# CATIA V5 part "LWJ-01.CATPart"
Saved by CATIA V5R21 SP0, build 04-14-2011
Part number: LWJ-01.SLDPRT
Bounding box of the stored display mesh (mm): x -1.362 to 1.338, y -0.976 to 1.024, z 2.1 to 2.7
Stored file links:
  C:\Users\user\Desktop\CATIA文件\0-最新文件(2025.3月之前的慎用)\LWJ-01\LWJ-01.CATPart
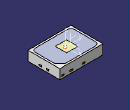
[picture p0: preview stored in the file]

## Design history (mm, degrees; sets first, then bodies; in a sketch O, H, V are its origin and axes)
AxisSystem1: origin (-0.0115, 0.0244, 2.7), X (0, 1, 0), Y (-1, 0, 0), Z (0, 0, 1)
Set1
  DatumSurface1 to DatumSurface42
  Line1: stored without definition
  Circle1: stored without definition
  Line2: stored without definition
  Circle2: stored without definition
  Line3: stored without definition
  Circle3: stored without definition
  Line4: stored without definition
  Circle4: stored without definition
  Line5: stored without definition
  Circle5: stored without definition
  Line6: stored without definition
  Circle6: stored without definition
  Line7: stored without definition
  Circle7: stored without definition
  Line8: stored without definition
  Line9: stored without definition
  Circle8: stored without definition
  Line10: stored without definition
  Line11: stored without definition
  Circle9: stored without definition
  Line12: stored without definition
  Line13: stored without definition
  Circle10: stored without definition
  Line14 to Line18: stored without definition
  Circle11: stored without definition
  Line19: stored without definition
  Circle12: stored without definition
  Line20: stored without definition
  Circle13: stored without definition
  Line21: stored without definition
  Circle14: stored without definition
  Line22: stored without definition
  Circle15: stored without definition
  Line23: stored without definition
  Circle16: stored without definition
  Line24: stored without definition
  Circle17: stored without definition
  Line25: stored without definition
  Circle18: stored without definition
  Line26: stored without definition
  Circle19: stored without definition
  Line27: stored without definition
  Circle20: stored without definition
  Line28 to Line30: stored without definition
  Circle21: stored without definition
  Line31: stored without definition
  Circle22: stored without definition
  Line32: stored without definition
  Circle23: stored without definition
  Line33: stored without definition
  Circle24: stored without definition
  Line34: stored without definition
  Line35: stored without definition
  Circle25: stored without definition
  Line36: stored without definition
  Circle26: stored without definition
  Line37: stored without definition
  Circle27: stored without definition
  Line38: stored without definition
  Circle28: stored without definition
  Line39: stored without definition
  Circle29: stored without definition
  Line40: stored without definition
  Circle30: stored without definition
  Line41: stored without definition
  Circle31: stored without definition
  Line42: stored without definition
  Circle32: stored without definition
  Line43: stored without definition
  Circle33: stored without definition
  Line44 to Line46: stored without definition
  Circle34: stored without definition
  Line47: stored without definition
  Circle35: stored without definition
  Line48: stored without definition
  Circle36: stored without definition
  Line49: stored without definition
  Circle37: stored without definition
  Line50: stored without definition
  Circle38: stored without definition
  Line51 to Line79: stored without definition
  DatumSurface43 to DatumSurface79
  Line80: stored without definition
  Circle39: stored without definition
  Line81: stored without definition
  Circle40: stored without definition
  Line82: stored without definition
  Circle41: stored without definition
  Line83: stored without definition
  Circle42: stored without definition
  Circle43: stored without definition
  Line84 to Line87: stored without definition
  Circle44: stored without definition
  Line88 to Line90: stored without definition
  Circle45: stored without definition
  Line91 to Line93: stored without definition
  Circle46: stored without definition
  Line94: stored without definition
  Line95: stored without definition
  Circle47: stored without definition
  Line96: stored without definition
  Circle48: stored without definition
  Line97: stored without definition
  Circle49: stored without definition
  Line98 to Line100: stored without definition
  Circle50: stored without definition
  Line101: stored without definition
  Circle51: stored without definition
  Line102: stored without definition
  Circle52: stored without definition
  Line103: stored without definition
  Circle53: stored without definition
  Line104: stored without definition
  Circle54: stored without definition
  Line105 to Line107: stored without definition
  Circle55: stored without definition
  Line108: stored without definition
  Circle56: stored without definition
  Line109 to Line112: stored without definition
  Circle57: stored without definition
  Line113: stored without definition
  Circle58: stored without definition
  Line114: stored without definition
  Circle59: stored without definition
  Line115 to Line117: stored without definition
  Circle60: stored without definition
  Line118: stored without definition
  Circle61: stored without definition
  Line119: stored without definition
  Circle62: stored without definition
  Line120: stored without definition
  Circle63: stored without definition
  Line121: stored without definition
  Circle64: stored without definition
  Line122 to Line124: stored without definition
  Circle65: stored without definition
  Line125: stored without definition
  Circle66: stored without definition
  Line126 to Line153: stored without definition
  DatumSurface80 to DatumSurface154
  DatumCurve1
  DatumCurve2
  Circle67: stored without definition
  Line154: stored without definition
  Circle68: stored without definition
  Line155: stored without definition
  Line156: stored without definition
  Circle69: stored without definition
  Line157: stored without definition
  Circle70: stored without definition
  Line158 to Line160: stored without definition
  Circle71: stored without definition
  Line161: stored without definition
  Circle72: stored without definition
  Line162 to Line164: stored without definition
  Circle73: stored without definition
  Line165: stored without definition
  Circle74: stored without definition
  Line166 to Line168: stored without definition
  Circle75: stored without definition
  Line169: stored without definition
  Circle76: stored without definition
  Line170: stored without definition
  Line171: stored without definition
  Circle77: stored without definition
  Line172: stored without definition
  Circle78: stored without definition
  Line173: stored without definition
  Circle79: stored without definition
  Line174 to Line176: stored without definition
  Circle80: stored without definition
  Line177: stored without definition
  Circle81: stored without definition
  Line178: stored without definition
  Circle82: stored without definition
  Line179: stored without definition
  Circle83: stored without definition
  Line180: stored without definition
  Circle84: stored without definition
  Line181 to Line183: stored without definition
  Circle85: stored without definition
  Line184: stored without definition
  Circle86: stored without definition
  Line185 to Line187: stored without definition
  Circle87: stored without definition
  Line188: stored without definition
  Line189: stored without definition
  Circle88: stored without definition
  Line190: stored without definition
  Line191: stored without definition
  Circle89: stored without definition
  Line192 to Line198: stored without definition
  Circle90: stored without definition
  Line199 to Line202: stored without definition
  Circle91: stored without definition
  Line203: stored without definition
  Line204: stored without definition
  Circle92: stored without definition
  Line205 to Line208: stored without definition
  Circle93: stored without definition
  Line209: stored without definition
  Line210: stored without definition
  Circle94: stored without definition
  Line211 to Line216: stored without definition
  Circle95: stored without definition
  Line217 to Line219: stored without definition
  Circle96: stored without definition
  Line220 to Line229: stored without definition
  Circle97: stored without definition
  Line230: stored without definition
  Circle98: stored without definition
  Line231: stored without definition
  Circle99: stored without definition
  Line232: stored without definition
  Circle100: stored without definition
  Line233: stored without definition
  Circle101: stored without definition
  Line234: stored without definition
  Circle102: stored without definition
  Line235: stored without definition
  Circle103: stored without definition
  Line236: stored without definition
  Circle104: stored without definition
  Line237 to Line245: stored without definition
  Circle105: stored without definition
  Line246: stored without definition
  Circle106: stored without definition
  Line247: stored without definition
  Circle107: stored without definition
  Line248: stored without definition
  Circle108: stored without definition
  Line249: stored without definition
  Circle109: stored without definition
  Line250: stored without definition
  Circle110: stored without definition
  Line251: stored without definition
  Circle111: stored without definition
  Line252: stored without definition
  Circle112: stored without definition
  Line253: stored without definition
  Circle113: stored without definition
  Line254: stored without definition
  Circle114: stored without definition
  Line255: stored without definition
  Circle115: stored without definition
  Line256: stored without definition
  Circle116: stored without definition
  Line257: stored without definition
  Circle117: stored without definition
  Line258 to Line260: stored without definition
  Circle118: stored without definition
  Line261: stored without definition
  Circle119: stored without definition
  Line262: stored without definition
  Circle120: stored without definition
  Line263: stored without definition
  Circle121: stored without definition
  Line264: stored without definition
  Circle122: stored without definition
  Line265: stored without definition
  Circle123: stored without definition
  Line266: stored without definition
  Circle124: stored without definition
  Line267: stored without definition
  Circle125: stored without definition
  Line268: stored without definition
  Circle126: stored without definition
  Line269: stored without definition
  Circle127: stored without definition
  Line270: stored without definition
  Circle128: stored without definition
  Line271 to Line273: stored without definition
  Circle129: stored without definition
  Line274: stored without definition
  Circle130: stored without definition
  Line275: stored without definition
  Circle131: stored without definition
  Line276: stored without definition
  Circle132: stored without definition
  Line277 to Line313: stored without definition
  DatumCurve3
  Line314: stored without definition
  DatumCurve4
  Line315: stored without definition
  DatumCurve5
  Line316: stored without definition
  DatumCurve6
  Line317: stored without definition
  DatumCurve7
  Line318 to Line323: stored without definition
  DatumCurve8
  Line324: stored without definition
  DatumCurve9
  Line325: stored without definition
  DatumCurve10
  Line326: stored without definition
  DatumCurve11
  Line327: stored without definition
  DatumCurve12
  Line328 to Line336: stored without definition
  Point1 "几何中心（测试中心）": type Between, FirstPoint vertex [face of DatumSurface148], SecondPoint vertex [face of DatumSurface147], Ratio 0.5
  Point2 "虚拟坐标": (-0.0551, 0.0355, -0.0789), relative to Point1, in AxisSystem1
Body1 (main body)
